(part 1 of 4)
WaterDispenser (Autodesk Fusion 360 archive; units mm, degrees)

design "WaterDispenser" references "Pump"
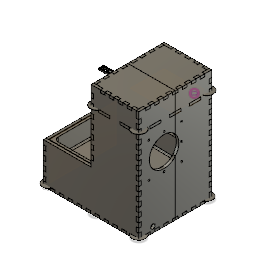
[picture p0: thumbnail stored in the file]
parameter "WaterContainerWidth" = 150
parameter "WaterContainerLenght" = 200
parameter "WaterDispenserHeight" = 75
parameter "WaterSensorFloatDiameter" = 24
parameter "WaterSensorBaseDiameter" = 9.8
parameter "LatexTubeDiameter" = 9.5
parameter "latexTubeInnerDiameter" = 6.5
parameter "WaterContainerCableHoleDiameter" = 14
parameter "WaterSensorCableGap" = 15
parameter "LatexTubeConnectionTightGap" = 0.5
parameter "WaterContainerBorderThickness" = 5
parameter "WaterContainerBorderHeight" = 10
parameter "WaterSensorBaseHeight" = 13
parameter "WaterSensorHeight" = 67.5
parameter "WaterContainerSlopeHeight" = 5
parameter "WaterContainerSensorHoleWith" = 70
parameter "WaterContainerSensorHoleLenght" = 50
parameter "WaterSensorAroundGap" = 10
parameter "WaterContainerHolePumpWidth" = 70
parameter "LatexTubeConnectionLength" = 20
parameter "LatexTubeConnectorToothLenth" = 4
parameter "LatextubeConnectionToothFiletHeight" = 0.4
parameter "WaterContainerSafetyHeightCable" = 20
parameter "WaterContainerElectricHoleDiameter" = 13
parameter "LatexTubeGapHole" = 0.4
parameter "WaterContainerHoleThickness" = 3
parameter "WaterContainerBottomSpaceWire" = 20
parameter "GapBetweenWoodPart" = 0.5
parameter "GapBetweenWaterContainer" = 1
parameter "WaterFallHeight" = 120
parameter "TopContainerHeight" = 40
parameter "WoodThickness" = 5.7
parameter "WoodTooth" = 10
parameter "WaterFallDiameter" = 6
parameter "WaterFallStopperDistance" = 10
parameter "WaterFountainHoleFront" = 15
parameter "WoodConnectionLength" = 25
parameter "AcDistanceHole" = 20
parameter "AcHoleDiameter" = 10
sketch "Sketch1" plane through (0, 0, 0) normal (0, 1, 0) x axis (1, 0, 0)
  line L1 (200, 0) -> (0, 0)
  line L2 (200, 150) -> (200, 0)
  line L3 (0, 150) -> (200, 150)
  line L4 (0, 0) -> (0, 150)
  point P1 (0, 0)
  point P2 (0, 0)
  point P3 (200, 0)
  horizontal L1
  vertical L2
  horizontal L3
  vertical L4
  coincident P1 P2
  dimension "d16" distance P2 P3 = 200 (= "WaterContainerLenght")
  dimension "d17" distance L1 L3 = 150 (= "WaterContainerWidth")
extrude "Extrude1" new body sketch "Sketch1" along normal blind 85 (= "WaterDispenserHeight + WaterContainerBorderHeight")
work_plane "WorkPlane1"
sketch "Sketch2" plane through (100, 42.5, -5) normal (0, 0, 1) x axis (1, 0, 0)
  line L1 (100, -42.5) -> (-100, -42.5)
  line L2 (100, 42.5) -> (100, -42.5)
  line L3 (-100, 42.5) -> (100, 42.5)
  line L4 (-100, -42.5) -> (-100, 42.5)
  line L5 (-95, -42.5) -> (-95, 42.5)
  line L6 (95, -42.5) -> (95, 42.5)
  line L7 (100, -14.5) -> (-100, -14.5)
  line L8 (100, -1.5) -> (-100, -1.5)
  line L9 (100, -27.5) -> (-100, -27.5)
  line L10 (100, 40) -> (-100, 40)
  line L11 (-100, -6.5) -> (100, -6.5)
  line L12 (100, 10) -> (-100, 10)
  line L13 (100, 3.5) -> (-100, 3.5)
  line L14 (-95, 3.5) -> (95, -1.5)
  line L15 (100, -1.5) -> (-100, -1.5)
  line L16 (95, -6.5) -> (-95, -1.5)
  line L17 (45, -42.5) -> (45, -0.1842)
  line L18 (40, -42.5) -> (40, -0.0526)
  line L19 (-100, 42.5) -> (-95, 42.5)
  line L20 (-100, -42.5) -> (-100, 42.5)
  line L21 (-95, -42.5) -> (-100, -42.5)
  line L22 (95, 42.5) -> (-95, 42.5)
  line L23 (-95, -42.5) -> (40, -42.5)
  point P6 (-95, 42.5)
  point P7 (-95, -42.5)
  point P8 (95, 42.5)
  point P9 (95, -42.5)
  point P10 (-100, -14.5)
  point P11 (100, -14.5)
  point P12 (-100, -1.5)
  point P13 (100, -1.5)
  point P14 (-100, -27.5)
  point P15 (100, -27.5)
  point P16 (-100, 40)
  point P17 (100, 40)
  point P18 (100, -6.5)
  point P19 (-100, -6.5)
  point P20 (-100, 10)
  point P21 (100, 10)
  point P22 (-100, 3.5)
  point P23 (100, 3.5)
  point P24 (95, -1.5)
  point P25 (-95, 3.5)
  point P26 (-100, -1.5)
  point P27 (100, -1.5)
  point P28 (-95, -1.5)
  point P29 (95, -6.5)
  point P30 (45, -0.1842)
  point P31 (45, -42.5)
  point P32 (40, -0.0526)
  point P33 (40, -42.5)
  point P5 (-100, 42.5)
  point P34 (-100, 42.5)
  point P2 (-100, -42.5)
  point P35 (-100, -42.5)
  point P36 (-100, -42.5)
  coincident L3 P6
  coincident L1 P7
  perpendicular L1 L5
  coincident L3 P8
  coincident L1 P9
  perpendicular L1 L6
  coincident L4 P10
  coincident L2 P11
  perpendicular L2 L7
  coincident L4 P12
  coincident L2 P13
  perpendicular L2 L8
  coincident L4 P14
  coincident L2 P15
  perpendicular L2 L9
  coincident L4 P16
  coincident L2 P17
  perpendicular L2 L10
  coincident L2 P18
  coincident L4 P19
  perpendicular L4 L11
  coincident L4 P20
  coincident L2 P21
  perpendicular L2 L12
  coincident L4 P22
  coincident L2 P23
  perpendicular L2 L13
  coincident L8 P24
  coincident L6 P24
  coincident L5 P25
  coincident L13 P25
  coincident L4 P26
  coincident L2 P27
  perpendicular L2 L15
  coincident L15 P28
  coincident L5 P28
  coincident L6 P29
  coincident L11 P29
  coincident L14 P30
  coincident L1 P31
  perpendicular L1 L17
  coincident L14 P32
  coincident L1 P33
  perpendicular L1 L18
  coincident P5 P34
  coincident P2 P35
  coincident P2 P36
  dimension "d21" distance L4 L5 = 5 (= "WaterContainerBorderThickness")
  dimension "d22" distance L2 L6 = 5 (= "WaterContainerBorderThickness")
  dimension "d23" distance L1 L8 = 41
  dimension "d24" distance L1 L7 = 28 (= "WaterSensorCableGap + WaterSensorBaseHeight")
  dimension "d29" distance L1 L9 = 15 (= "WaterSensorCableGap")
  dimension "d30" distance L9 L10 = 67.5 (= "WaterSensorHeight")
  dimension "d32" distance L8 L11 = 5 (= "WaterContainerBorderThickness")
  dimension "d33" distance L8 L13 = 5 (= "WaterContainerSlopeHeight")
  dimension "d34" distance L11 L15 = 5 (= "WaterContainerSlopeHeight")
  dimension "d37" distance L6 L17 = 50 (= "WaterContainerSensorHoleLenght")
  dimension "d38" distance L17 L18 = 5 (= "WaterContainerBorderThickness")
extrude "Extrude2" cut sketch "Sketch2" profile of L1 L3 L5 L6 L14 L16 L18 L22 L23 against normal blind 140 (magnitude of "-( WaterContainerWidth - 2 * WaterContainerBorderThickness )")
work_plane "WorkPlane2"
sketch "Sketch4" plane through (100, 20, -75) normal (0, -1, 0) x axis (1, 0, 0)
  line L1 (-95, 70) -> (-95, -70)
  line L2 (40, 70) -> (-95, 70)
  line L3 (40, -70) -> (40, 70)
  line L4 (-95, -70) -> (40, -70)
  line L5 (-100, -75) -> (-100, 75)
  line L6 (100, -75) -> (-100, -75)
  line L7 (100, 75) -> (100, -75)
  line L8 (-100, 75) -> (100, 75)
  line L9 (40, 0) -> (100, 0)
  line L10 (95, -75) -> (95, 75)
  line L11 (73, -75) -> (73, 75)
  line L12 (56, 35) -> (90, 35)
  line L13 (56, -35) -> (56, 35)
  line L14 (90, -35) -> (56, -35)
  line L15 (90, 35) -> (90, -35)
  line L16 (56, -35) -> (90, 35)
  line L17 (90, -35) -> (56, 35)
  point P10 (100, 0)
  point P11 (40, 0)
  point P12 (95, 75)
  point P13 (95, -75)
  point P14 (73, 75)
  point P15 (73, -75)
  point P20 (73, 0)
  point P18 (56, -35)
  point P19 (90, -35)
  midpoint L7 P10
  midpoint L3 P11
  coincident L8 P12
  coincident L6 P13
  perpendicular L6 L10
  coincident L8 P14
  coincident L6 P15
  perpendicular L6 L11
  perpendicular L12 L13
  parallel L12 L14
  parallel L13 L15
  horizontal L12
  coincident L16 P20
  coincident L17 P20
  midpoint L11 P20
  dimension "d44" distance L10 L11 = 22 (= "WaterSensorAroundGap + ( WaterSensorFloatDiameter / 2 )")
  dimension "d45" distance L7 L10 = 5 (= "WaterContainerBorderThickness")
  dimension "d47" distance P18 P19 = 34 (= "WaterSensorFloatDiameter + WaterSensorAroundGap")
  dimension "d48" distance L12 L14 = 70 (= "WaterContainerHolePumpWidth")
extrude "Extrude3" cut sketch "Sketch4" profile of L12 L13 L14 L15 to an object
chamfer "Chamfer4" distance 20
fillet "Fillet7" radius 40
fillet "Fillet8" radius 20.54
fillet "Fillet9" radius 30
fillet "Fillet10" radius 50
sketch "Sketch6" plane through (0, 20, 0) normal (0, 1, 0) x axis (-1, 0, 0)
  line L1 (-156, -110) -> (-190, -110)
  line L2 (-156, -40) -> (-156, -110)
  line L3 (-190, -40) -> (-156, -40)
  line L4 (-156, -75) -> (-190, -75)
  line L5 (-173, -40) -> (-173, -110)
  line L6 (-190, -110) -> (-190, -40)
  circle C1 centre (-173, -75) radius 4.9
  point P9 (-156, -75)
  point P10 (-173, -110)
  point P11 (-173, -40)
  point P12 (-173, -75)
  midpoint L2 P9
  midpoint L1 P10
  midpoint L3 P11
  midpoint L4 P12
  dimension "d78" diameter C1 = 9.8 (= "WaterSensorBaseDiameter")
extrude "Extrude7" cut sketch "Sketch6" profile of C1 to an object
sketch "Sketch7" plane through (0, 0, 0) normal (0, -1, 0) x axis (1, 0, 0)
  line L1 (5, -5) -> (5, -145)
  line L2 (140, -5) -> (5, -5)
  line L3 (140, -145) -> (140, -5)
  line L4 (5, -145) -> (140, -145)
  line L5 (0, -150) -> (0, 0)
  line L6 (200, -150) -> (0, -150)
  line L7 (200, 0) -> (200, -150)
  line L8 (0, 0) -> (200, 0)
  line L9 (5, -5) -> (140, -5)
  line L10 (5, -145) -> (5, -5)
  line L11 (140, -145) -> (5, -145)
  line L12 (140, -5) -> (140, -145)
  line L13 (200, -5) -> (140, -5)
  line L14 (200, -145) -> (140, -145)
  line L15 (195, -145) -> (195, -5)
  circle C1 centre (173, -75) radius 4.9
  point P11 (140, -5)
  point P15 (140, -5)
  point P16 (200, -5)
  point P14 (140, -145)
  point P17 (140, -145)
  point P18 (200, -145)
  point P19 (195, -5)
  point P20 (195, -145)
  coincident P11 P15
  coincident L7 P16
  perpendicular L7 L13
  coincident P14 P17
  coincident L7 P18
  perpendicular L7 L14
  coincident L13 P19
  coincident L14 P20
  perpendicular L14 L15
  dimension "d81" distance L7 L15 = 5 (= "WaterContainerBorderThickness")
extrude "Extrude8" cut sketch "Sketch7" profile of C1 L3 L12 L13 L14 L15 no distance stored
sketch "Sketch8" plane through (140, 0, 0) normal (-1, 0, 0) x axis (0, 0, 1)
  line L1 (-5, 15) -> (-145, 15)
  line L2 (-5, 37.4474) -> (-5, 15)
  line L3 (-145, 37.4474) -> (-5, 37.4474)
  line L4 (-145, 15) -> (-145, 37.4474)
  line L5 (-110, 20) -> (-40, 20)
  line L6 (-38.8581, 22.0197) -> (-111.1419, 22.0197)
  line L7 (-75, 20) -> (-75, 22.0197)
  line L8 (-39.9729, 22.0197) -> (-40, 20)
  line L9 (-75, 19.5953) -> (-50.0021, 19.5953)
  line L10 (-62.5011, 20) -> (-62.5011, 19.5953)
  curve K1 (-40, 20) -> (-38.8581, 22.0197)
  curve K2 (-111.1419, 22.0197) -> (-110, 20)
  circle C1 centre (-62.5011, 23.25) radius 3.25
  circle C2 centre (-62.5011, 23.25) radius 4.75
  point P10 (-75, 22.0197)
  point P11 (-75, 20)
  point P6 (-40, 20)
  point P12 (-40, 20)
  point P13 (-39.9729, 22.0197)
  point P15 (-75, 19.5953)
  point P16 (-62.5011, 19.5953)
  point P17 (-62.5011, 20)
  midpoint L6 P10
  midpoint L5 P11
  coincident P6 P12
  coincident L6 P13
  coincident L7 P15
  perpendicular L7 L9
  midpoint L9 P16
  coincident L5 P17
  perpendicular L5 L10
  coincident P17 C1
  concentric C1 C2
  dimension "d84" diameter C1 = 6.5 (= "latexTubeInnerDiameter")
  dimension "d85" diameter C2 = 9.5 (= "LatexTubeDiameter")
extrude "Extrude9" cut sketch "Sketch8" profile of C1 to an object
extrude "Extrude10" new body sketch "Sketch8" profile of L5 L6 C1 C2 along normal blind 20 (= "LatexTubeConnectionLength")
work_plane "WorkPlane3" AlongDistance -62.501
sketch "Sketch9" plane through (100, 42.5, -62.5011) normal (0, 0, 1) x axis (1, 0, 0)
  line L1 (20, -24) -> (20, -14.5)
  line L2 (40, -24) -> (40, -14.5)
  line L3 (39, -14) -> (25, -14)
  line L4 (40, -14.5) -> (20, -14.5)
  line L5 (24, -14.5) -> (24, -14.4)
  curve K1 (23.3029, -14.1322) -> (20, -14.5)
  line L6 (17, -19.25) -> (40, -19.25)
  arc A1 centre (23.6, -14.4) radius 0.4 clockwise from (23.3029, -14.1322) to (24, -14.4)
  point P2 (20, -14.5)
  point P8 (20, -14.5)
  point P4 (40, -14.5)
  point P9 (40, -14.5)
  point P10 (24, -14.5)
  point P11 (20, -14.5)
  point P13 (40, -19.25)
  point P17 (24, -14.4)
  horizontal L3
  coincident P2 P8
  coincident P4 P9
  coincident L4 P10
  perpendicular L4 L5
  coincident P8 P11
  midpoint L2 P13
  perpendicular L1 L6
  tangent K1 A1
  tangent L5 A1
  dimension "d93" distance P2 L3 = 0.5 (= "LatexTubeConnectionTightGap")
  dimension "d94" distance P8 L5 = 4 (= "LatexTubeConnectorToothLenth")
  dimension "d100" radius A1 = 0.4 (= "LatextubeConnectionToothFiletHeight")
  dimension "d102" distance P10 P17 = 0.1 (= "LatexTubeConnectionTightGap - LatextubeConnectionToothFiletHeight")
work_plane "WorkPlane4" AlongDistance 20 (= "WaterContainerSafetyHeightCable")
sketch "Sketch10" plane through (100, 105, -75) normal (0, 1, 0) x axis (1, 0, 0)
  line L1 (-95, 70) -> (-95, -70)
  line L2 (95, 70) -> (-95, 70)
  line L3 (95, -70) -> (95, 70)
  line L4 (-95, -70) -> (95, -70)
  line L5 (-100, -75) -> (-100, 75)
  line L6 (100, -75) -> (-100, -75)
  line L7 (100, 75) -> (100, -75)
  line L8 (-100, 75) -> (100, 75)
  line L9 (60.169, 60.5) -> (60.169, 70)
  line L10 (87.05, 54.1) -> (95, 54.1)
  circle C1 centre (87.05, 62.05) radius 4.95
  circle C2 centre (87.05, 62.05) radius 7.95
  circle C3 centre (69.669, 60.5) radius 6.5
  circle C4 centre (69.669, 60.5) radius 9.5
  point P14 (60.169, 70)
  point P15 (60.169, 60.5)
  point P16 (95, 54.1)
  point P17 (87.05, 54.1)
  concentric C1 C2
  concentric C3 C4
  tangent L2 C2
  tangent L2 C4
  tangent L3 C2
  tangent C2 C4
  coincident L2 P14
  coincident C4 P15
  tangent C4 L9
  perpendicular L2 L9
  coincident L3 P16
  coincident C2 P17
  tangent C2 L10
  perpendicular L3 L10
  dimension "d108" diameter C1 = 9.9 (= "LatexTubeDiameter + LatexTubeGapHole")
  dimension "d110" distance C1 C2 = 3 (= "WaterContainerHoleThickness")
  dimension "d112" diameter C3 = 13 (= "WaterContainerElectricHoleDiameter")
  dimension "d113" distance C3 C4 = 3 (= "WaterContainerHoleThickness")
extrude "Extrude11" cut sketch "Sketch10" profile of L2 L3 C1 C2 C3 C4 L9 L10 to an object
sketch "Sketch11" plane through (0, 15, 0) normal (0, -1, 0) x axis (1, 0, 0)
  line L1 (195, -5) -> (195, -129.1)
  line L2 (140, -5) -> (195, -5)
  line L3 (140, -145) -> (140, -5)
  line L4 (160.169, -145) -> (140, -145)
  line L5 (160.169, -126) -> (160.169, -145)
  line L6 (195, -126) -> (160.169, -126)
  line L7 (160.169, -135.5) -> (160.169, -145)
  line L8 (195, -129.1) -> (187.05, -129.1)
  line L9 (140, -126) -> (160.169, -126)
  arc A1 centre (169.669, -135.5) radius 9.5 clockwise from (160.169, -135.5) to (179.1314, -136.3438)
  arc A2 centre (187.05, -137.05) radius 7.95 clockwise from (179.1314, -136.3438) to (187.05, -129.1)
  circle C1 centre (173, -75) radius 4.9
  arc A3 centre (169.669, -135.5) radius 9.5 clockwise from (160.169, -135.5) to (179.1314, -136.3438)
  arc A4 centre (187.05, -137.05) radius 7.95 clockwise from (179.1314, -136.3438) to (187.05, -129.1)
  point P16 (160.169, -145)
  point P18 (195, -126)
  point P21 (140, -126)
  coincident L4 P16
  perpendicular L4 L5
  coincident L1 P18
  perpendicular L1 L6
  tangent A1 L5
  tangent A3 L6
  coincident L3 P21
  perpendicular L3 L9
extrude "Extrude12" cut sketch "Sketch11" profile of A1 A2 L1 L3 L4 A3 A4 L5 L6 L7 L8 L9 no distance stored
extrude "Extrude13" new body sketch "Sketch10" profile of L2 L3 C1 C2 C3 C4 L9 L10 to an object
fillet "Fillet12" radius 5
combine "Combine1"
fillet "Fillet13" radius 8
extrude "Extrude14" add of existing geometry to an object
extrude "Extrude15" add of existing geometry to an object
fillet "Fillet14" radius 10
fillet "Fillet15" radius 3
fillet "Fillet16" radius 3
fillet "Fillet18" radius 10
work_plane "WorkPlane5" AlongDistance 1 (= "GapBetweenWaterContainer")
work_plane "WorkPlane6" AlongDistance 1 (= "GapBetweenWaterContainer")
sketch "Sketch12" plane through (100, 42.5, 1) normal (0, 0, 1) x axis (1, 0, 0)
  line L1 (-106.7, -48.2) -> (-106.7, 42.5)
  line L2 (106.7, 202.5) -> (106.7, -48.2)
  line L3 (0, 202.5) -> (106.7, 202.5)
  line L4 (0, 42.5) -> (0, 202.5)
  line L5 (-106.7, 42.5) -> (0, 42.5)
  line L6 (100, -42.5) -> (-100, -42.5)
  line L7 (100, 42.5) -> (100, -42.5)
  line L8 (-100, 42.5) -> (100, 42.5)
  line L9 (-100, -42.5) -> (-100, 42.5)
  line L10 (106.7, -48.2) -> (-106.7, -48.2)
  point P11 (-100, 42.5)
  point P1 (0, 0)
  point P4 (106.7, -48.2)
  point P13 (106.7, -48.2)
  point P3 (-106.7, -48.2)
  point P12 (-106.7, -48.2)
  vertical L1
  perpendicular L1 L3
  perpendicular L1 L5
  coincident L5 P11
  coincident P1 L4
  perpendicular L1 L10
  coincident P4 P13
  coincident P3 P12
  dimension "d137" distance L1 L9 = 6.7 (= "GapBetweenWaterContainer + WoodThickness")
  dimension "d138" distance L2 L7 = 6.7 (= "GapBetweenWaterContainer + WoodThickness")
  dimension "d140" distance L3 L8 = 160 (= "WaterFallHeight + TopContainerHeight")
  dimension "d145" distance L6 L10 = 5.7 (= "WoodThickness")
sketch "Sketch13" plane through (-1, 42.5, -75) normal (-1, 0, 0) x axis (0, 0, -1)
  line L1 (-76, 48.2) -> (-76, -42.5)
  line L2 (-75, 42.5) -> (75, 42.5)
  line L3 (75, -42.5) -> (75, 42.5)
  line L4 (-75, -42.5) -> (75, -42.5)
  line L5 (-81.7, -42.5) -> (81.7, -42.5)
  line L6 (81.7, 48.2) -> (-81.7, 48.2)
  line L7 (81.7, -42.5) -> (81.7, 48.2)
  line L8 (-81.7, 48.2) -> (-81.7, -42.5)
  line L9 (0, 48.2) -> (0, -42.5)
  point P7 (-75, -42.5)
  point P11 (-81.7, -42.5)
  point P12 (0, -42.5)
  point P13 (0, 48.2)
  horizontal L5
  horizontal L6
  vertical L7
  coincident P7 L5
  perpendicular L5 L8
  coincident L5 P11
  midpoint L4 P12
  midpoint L6 P13
  dimension "d149" distance L3 L7 = 6.7 (= "WoodThickness + GapBetweenWaterContainer")
  dimension "d150" distance L2 L6 = 5.7 (= "WoodThickness")
  dimension "d151" distance L1 L8 = 5.7 (= "WoodThickness")
extrude "Extrude1" new body sketch "Sketch12" along normal blind 5.7 (= "WoodThickness")
sketch "Sketch1" plane through (0, 0, 6.7) normal (0, 0, 1) x axis (1, 0, 0)
  line L1 (206.7, -5.7) -> (-6.7, -5.7)
  line L2 (206.7, 245) -> (206.7, -5.7)
  line L3 (100, 245) -> (206.7, 245)
  line L4 (100, 85) -> (100, 245)
  line L5 (-6.7, 85) -> (100, 85)
  line L6 (-6.7, -5.7) -> (-6.7, 85)
  line L7 (-1, 85) -> (-6.7, 85)
  line L8 (-1, 75) -> (-1, 85)
  line L9 (-6.7, 75) -> (-1, 75)
  line L10 (-6.7, 85) -> (-6.7, 75)
  line L11 (-1, 75) -> (-6.7, 75)
  line L12 (-1, 65) -> (-1, 75)
  line L13 (-6.7, 65) -> (-1, 65)
  line L14 (-6.7, 75) -> (-6.7, 65)
  line L15 (-6.7, 55) -> (-1, 55)
  line L16 (-1, 45) -> (-1, 55)
  line L17 (-6.7, 45) -> (-1, 45)
  line L18 (-6.7, 55) -> (-6.7, 45)
  line L19 (-6.7, 35) -> (-1, 35)
  line L20 (-1, 25) -> (-1, 35)
  line L21 (-6.7, 25) -> (-1, 25)
  line L22 (-6.7, 35) -> (-6.7, 25)
  line L23 (-6.7, 15) -> (-1, 15)
  line L24 (-1, 5) -> (-1, 15)
  line L25 (-6.7, 5) -> (-1, 5)
  line L26 (-6.7, 15) -> (-6.7, 5)
  point P7 (-6.7, 85)
  point P8 (-6.7, 85)
  point P11 (-6.7, 75)
  point P9 (-1, 85)
  point P14 (-6.7, 65)
  horizontal L7
  vertical L8
  horizontal L9
  vertical L10
  coincident P7 P8
  horizontal L11
  vertical L12
  horizontal L13
  vertical L14
  dimension "d155" distance P8 P11 = 10 (= "WoodTooth")
  dimension "d156" distance P8 P9 = 5.7 (= "WoodThickness")
  dimension "d157" distance P11 P14 = 10 (= "WoodTooth")
  dimension "d158" distance L12 L14 = 5.7 (= "WoodThickness")
  dimension "d163" R-Pattern1-uDistance = -60
  dimension "d164" R-Pattern1-vDistance = -20 (= "-2 * WoodTooth")
extrude "Extrude3" cut sketch "Sketch1" profile of L6 L9 L11 L12 L13 L14 L15 L16 L17 L18 L19 L20 L21 L22 L23 L24 L25 L26 to an object
sketch "Sketch3" plane through (0, 0, 6.7) normal (0, 0, 1) x axis (1, 0, 0)
  line L1 (-1, 55) -> (-6.7, 55)
  line L2 (-1, 45) -> (-1, 55)
  line L3 (-6.7, 45) -> (-1, 45)
  line L4 (-6.7, 35) -> (-6.7, 45)
  line L5 (-1, 35) -> (-6.7, 35)
  line L6 (-1, 25) -> (-1, 35)
  line L7 (-6.7, 25) -> (-1, 25)
  line L8 (-6.7, 15) -> (-6.7, 25)
  line L9 (-1, 15) -> (-6.7, 15)
  line L10 (-1, 5) -> (-1, 15)
  line L11 (-6.7, 5) -> (-1, 5)
  line L12 (-6.7, -5.7) -> (-6.7, 5)
  line L13 (206.7, -5.7) -> (-6.7, -5.7)
  line L14 (206.7, 245) -> (206.7, -5.7)
  line L15 (100, 245) -> (206.7, 245)
  line L16 (100, 85) -> (100, 245)
  line L17 (-6.7, 85) -> (100, 85)
  line L18 (-6.7, 75) -> (-6.7, 85)
  line L19 (-1, 75) -> (-6.7, 75)
  line L20 (-1, 65) -> (-1, 75)
  line L21 (-6.7, 65) -> (-1, 65)
  line L22 (-6.7, 55) -> (-6.7, 65)
  line L23 (9, -5.7) -> (-1, -5.7)
  line L24 (9, 0) -> (9, -5.7)
  line L25 (-1, 0) -> (9, 0)
  line L26 (-1, -5.7) -> (-1, 0)
  line L27 (-1, -5.7) -> (-1, 85)
  line L28 (9, 0) -> (19, 0)
  line L29 (9, -5.7) -> (9, 0)
  line L30 (19, 0) -> (19, -5.7)
  line L31 (19, -5.7) -> (9, -5.7)
  line L32 (19, 0) -> (29, 0)
  line L33 (19, -5.7) -> (19, 0)
  line L34 (29, 0) -> (29, -5.7)
  line L35 (29, -5.7) -> (19, -5.7)
  line L36 (29, 0) -> (39, 0)
  line L37 (29, -5.7) -> (29, 0)
  line L38 (39, 0) -> (39, -5.7)
  line L39 (39, -5.7) -> (29, -5.7)
  line L40 (39, 0) -> (49, 0)
  line L41 (39, -5.7) -> (39, 0)
  line L42 (49, 0) -> (49, -5.7)
  line L43 (49, -5.7) -> (39, -5.7)
  line L44 (49, 0) -> (59, 0)
  line L45 (49, -5.7) -> (49, 0)
  line L46 (59, 0) -> (59, -5.7)
  line L47 (59, -5.7) -> (49, -5.7)
  line L48 (59, 0) -> (69, 0)
  line L49 (59, -5.7) -> (59, 0)
  line L50 (69, 0) -> (69, -5.7)
  line L51 (69, -5.7) -> (59, -5.7)
  line L52 (69, 0) -> (79, 0)
  line L53 (69, -5.7) -> (69, 0)
  line L54 (79, 0) -> (79, -5.7)
  line L55 (79, -5.7) -> (69, -5.7)
  line L56 (79, 0) -> (89, 0)
  line L57 (79, -5.7) -> (79, 0)
  line L58 (89, 0) -> (89, -5.7)
  line L59 (89, -5.7) -> (79, -5.7)
  line L60 (89, 0) -> (99, 0)
  line L61 (89, -5.7) -> (89, 0)
  line L62 (99, 0) -> (99, -5.7)
  line L63 (99, -5.7) -> (89, -5.7)
  line L64 (99, 0) -> (109, 0)
  line L65 (99, -5.7) -> (99, 0)
  line L66 (109, 0) -> (109, -5.7)
  line L67 (109, -5.7) -> (99, -5.7)
  line L68 (109, 0) -> (119, 0)
  line L69 (109, -5.7) -> (109, 0)
  line L70 (119, 0) -> (119, -5.7)
  line L71 (119, -5.7) -> (109, -5.7)
  line L72 (119, 0) -> (129, 0)
  line L73 (119, -5.7) -> (119, 0)
  line L74 (129, 0) -> (129, -5.7)
  line L75 (129, -5.7) -> (119, -5.7)
  line L76 (129, 0) -> (139, 0)
  line L77 (129, -5.7) -> (129, 0)
  line L78 (139, 0) -> (139, -5.7)
  line L79 (139, -5.7) -> (129, -5.7)
  line L80 (139, 0) -> (149, 0)
  line L81 (139, -5.7) -> (139, 0)
  line L82 (149, 0) -> (149, -5.7)
  line L83 (149, -5.7) -> (139, -5.7)
  line L84 (149, 0) -> (159, 0)
  line L85 (149, -5.7) -> (149, 0)
  line L86 (159, 0) -> (159, -5.7)
  line L87 (159, -5.7) -> (149, -5.7)
  line L88 (159, 0) -> (169, 0)
  line L89 (159, -5.7) -> (159, 0)
  line L90 (169, 0) -> (169, -5.7)
  line L91 (169, -5.7) -> (159, -5.7)
  line L92 (169, 0) -> (179, 0)
  line L93 (169, -5.7) -> (169, 0)
  line L94 (179, 0) -> (179, -5.7)
  line L95 (179, -5.7) -> (169, -5.7)
  line L96 (179, 0) -> (189, 0)
  line L97 (179, -5.7) -> (179, 0)
  line L98 (189, 0) -> (189, -5.7)
  line L99 (189, -5.7) -> (179, -5.7)
  line L100 (189, 0) -> (199, 0)
  line L101 (189, -5.7) -> (189, 0)
  line L102 (199, 0) -> (199, -5.7)
  line L103 (199, -5.7) -> (189, -5.7)
  line L104 (201, 0) -> (206.7, 0)
  line L105 (201, 10) -> (201, 0)
  line L106 (206.7, 10) -> (201, 10)
  line L107 (206.7, 0) -> (206.7, 10)
  line L108 (206.7, 20) -> (201, 20)
  line L109 (201, 10) -> (206.7, 10)
  line L110 (201, 20) -> (201, 10)
  line L111 (206.7, 10) -> (206.7, 20)
  line L112 (206.7, 30) -> (201, 30)
  line L113 (201, 20) -> (206.7, 20)
  line L114 (201, 30) -> (201, 20)
  line L115 (206.7, 20) -> (206.7, 30)
  line L116 (206.7, 40) -> (201, 40)
  line L117 (201, 30) -> (206.7, 30)
  line L118 (201, 40) -> (201, 30)
  line L119 (206.7, 30) -> (206.7, 40)
  line L120 (206.7, 50) -> (201, 50)
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  point P24 (-1, -5.7)
  point P27 (-1, 0)
  point P106 (206.7, 0)
  point P102 (199, 0)
  point P242 (100, 239.3)
  point P16 (206.7, 245)
  point P243 (206.7, 245)
  point P244 (206.7, 245)
  point P25 (9, -5.7)
  point P107 (201, 0)
  point P109 (206.7, 10)
  point P202 (201, 239.3)
  point P205 (201, 245)
  point P203 (191, 239.3)
  point P245 (105.7, 239.3)
  point P247 (100, 229.3)
  horizontal L23
  vertical L24
  horizontal L25
  vertical L26
  coincident L13 P24
  coincident P27 L27
  horizontal L104
  vertical L105
  horizontal L106
  vertical L107
  coincident L14 P106
  coincident P102 L104
  coincident L16 P242
  coincident P16 P243
  coincident P16 P244
  dimension "d189" distance P24 P27 = 5.7 (= "WoodThickness")
  dimension "d190" distance P24 P25 = 10 (= "WoodTooth")
  dimension "d197" distance P106 P107 = 5.7 (= "WoodThickness")
  dimension "d198" distance P106 P109 = 10 (= "WoodTooth")
  dimension "d203" distance P202 P205 = 5.7 (= "WoodThickness")
  dimension "d204" distance P202 P203 = 10 (= "WoodTooth")
  dimension "d209" distance P242 P245 = 5.7 (= "WoodThickness")
  dimension "d210" distance P242 P247 = 10 (= "WoodTooth")
  dimension "d193" R-Pattern1-uDistance = 10 (= "WoodTooth")
  dimension "d194" R-Pattern1-vDistance = 0
  dimension "d201" R-Pattern2-uDistance = 0
  dimension "d202" R-Pattern2-vDistance = 10 (= "WoodTooth")
  dimension "d208" R-Pattern3-vDistance = 0
  dimension "d213" R-Pattern4-uDistance = 0
extrude "Extrude7" cut sketch "Sketch3" to an object
work_plane "WorkPlane1"
mirror "Mirror1"
sketch "Sketch4" plane through (0, 0, 0) normal (-1, 0, 0) x axis (0, 0, 1)
  line L1 (0, 0) -> (-150, 0)
  line L2 (0, 85) -> (0, 0)
  line L3 (-150, 85) -> (0, 85)
  line L4 (-150, 0) -> (-150, 85)
work_plane "WorkPlane1" sketch "Sketch4" AlongDistance 1 (= "GapBetweenWaterContainer")
sketch "Sketch2" plane through (-1, 42.5, -75) normal (-1, 0, 0) x axis (0, 0, -1)
  line L1 (-81.7, -32.5) -> (-76, -32.5)
  line L2 (-81.7, -42.5) -> (-81.7, -32.5)
  line L3 (-76, -42.5) -> (-81.7, -42.5)
  line L4 (-76, -32.5) -> (-76, -42.5)
  line L5 (-81.7, -12.5) -> (-76, -12.5)
  line L6 (-81.7, -22.5) -> (-81.7, -12.5)
  line L7 (-76, -22.5) -> (-81.7, -22.5)
  line L8 (-76, -12.5) -> (-76, -22.5)
  line L9 (-76, -2.5) -> (-81.7, -2.5)
  line L10 (-76, 7.5) -> (-76, -2.5)
  line L11 (-81.7, 7.5) -> (-76, 7.5)
  line L12 (-81.7, -2.5) -> (-81.7, 7.5)
  line L13 (-76, 17.5) -> (-81.7, 17.5)
  line L14 (-76, 27.5) -> (-76, 17.5)
  line L15 (-81.7, 27.5) -> (-76, 27.5)
  line L16 (-81.7, 17.5) -> (-81.7, 27.5)
  line L17 (-76, 37.5) -> (-81.7, 37.5)
  line L18 (-76, 48.2) -> (-76, 37.5)
  line L19 (-81.7, 48.2) -> (-76, 48.2)
  line L20 (-81.7, 37.5) -> (-81.7, 48.2)
  line L21 (-75, 42.5) -> (75, 42.5)
  line L22 (-75, -42.5) -> (-75, 42.5)
  line L23 (75, -42.5) -> (-75, -42.5)
  line L24 (75, 42.5) -> (75, -42.5)
  line L25 (0, 42.5) -> (0, -42.5)
  line L26 (0, 48.2) -> (0, 42.5)
  line L27 (-76, 48.2) -> (0, 48.2)
  line L28 (-76, 48.2) -> (-76, 37.5)
  line L29 (-81.7, 37.5) -> (-76, 37.5)
  line L30 (-81.7, 27.5) -> (-81.7, 37.5)
  line L31 (-76, 27.5) -> (-81.7, 27.5)
  line L32 (-76, 17.5) -> (-76, 27.5)
  line L33 (-81.7, 17.5) -> (-76, 17.5)
  line L34 (-81.7, 7.5) -> (-81.7, 17.5)
  line L35 (-76, 7.5) -> (-81.7, 7.5)
  line L36 (-76, -2.5) -> (-76, 7.5)
  line L37 (-76, -2.5) -> (-81.7, -2.5)
  line L38 (-81.7, -12.5) -> (-81.7, -2.5)
  line L39 (-76, -12.5) -> (-81.7, -12.5)
  line L40 (-76, -22.5) -> (-76, -12.5)
  line L41 (-81.7, -22.5) -> (-76, -22.5)
  line L42 (-81.7, -32.5) -> (-81.7, -22.5)
  line L43 (-76, -32.5) -> (-81.7, -32.5)
  line L44 (-76, -42.5) -> (-76, -32.5)
  line L45 (0, -42.5) -> (-76, -42.5)
  line L46 (-76, 42.5) -> (-75, 42.5)
  line L47 (-66, 42.5) -> (-76, 42.5)
  line L48 (-66, 48.2) -> (-66, 42.5)
  line L49 (-76, 48.2) -> (-66, 48.2)
  line L50 (-76, 42.5) -> (-76, 48.2)
  line L51 (-56, 42.5) -> (-66, 42.5)
  line L52 (-56, 48.2) -> (-56, 42.5)
  line L53 (-66, 48.2) -> (-56, 48.2)
  line L54 (-66, 42.5) -> (-66, 48.2)
  line L55 (-46, 42.5) -> (-56, 42.5)
  line L56 (-46, 48.2) -> (-46, 42.5)
  line L57 (-56, 48.2) -> (-46, 48.2)
  line L58 (-56, 42.5) -> (-56, 48.2)
  line L59 (-36, 42.5) -> (-46, 42.5)
  line L60 (-36, 48.2) -> (-36, 42.5)
  line L61 (-46, 48.2) -> (-36, 48.2)
  line L62 (-46, 42.5) -> (-46, 48.2)
  line L63 (-26, 42.5) -> (-36, 42.5)
  line L64 (-26, 48.2) -> (-26, 42.5)
  line L65 (-36, 48.2) -> (-26, 48.2)
  line L66 (-36, 42.5) -> (-36, 48.2)
  line L67 (-16, 42.5) -> (-26, 42.5)
  line L68 (-16, 48.2) -> (-16, 42.5)
  line L69 (-26, 48.2) -> (-16, 48.2)
  line L70 (-26, 42.5) -> (-26, 48.2)
  line L71 (-6, 42.5) -> (-16, 42.5)
  line L72 (-6, 48.2) -> (-6, 42.5)
  line L73 (-16, 48.2) -> (-6, 48.2)
  line L74 (-16, 42.5) -> (-16, 48.2)
  point P26 (0, -42.5)
  point P27 (0, 42.5)
  point P20 (-76, 48.2)
  point P29 (-76, 48.2)
  point P19 (-76, 37.5)
  point P30 (-76, 37.5)
  point P31 (-76, 37.5)
  point P18 (-81.7, 37.5)
  point P32 (-81.7, 37.5)
  point P33 (-81.7, 37.5)
  point P17 (-81.7, 27.5)
  point P34 (-81.7, 27.5)
  point P35 (-81.7, 27.5)
  point P16 (-76, 27.5)
  point P36 (-76, 27.5)
  point P37 (-76, 27.5)
  point P15 (-76, 17.5)
  point P38 (-76, 17.5)
  point P14 (-81.7, 17.5)
  point P39 (-81.7, 17.5)
  point P40 (-81.7, 17.5)
  point P13 (-81.7, 7.5)
  point P41 (-81.7, 7.5)
  point P12 (-76, 7.5)
  point P42 (-76, 7.5)
  point P11 (-76, -2.5)
  point P43 (-76, -2.5)
  point P10 (-81.7, -2.5)
  point P44 (-81.7, -2.5)
  point P45 (-76, -2.5)
  point P46 (-81.7, -2.5)
  point P7 (-81.7, -12.5)
  point P47 (-81.7, -12.5)
  point P48 (-81.7, -12.5)
  point P6 (-76, -12.5)
  point P49 (-76, -12.5)
  point P9 (-76, -22.5)
  point P50 (-76, -22.5)
  point P8 (-81.7, -22.5)
  point P51 (-81.7, -22.5)
  point P52 (-81.7, -22.5)
  point P3 (-81.7, -32.5)
  point P53 (-81.7, -32.5)
  point P54 (-81.7, -32.5)
  point P2 (-76, -32.5)
  point P55 (-76, -32.5)
  point P56 (-76, -32.5)
  point P5 (-76, -42.5)
  point P57 (-76, -42.5)
  point P58 (-76, -42.5)
  point P23 (-75, 42.5)
  point P59 (-75, 42.5)
  point P60 (-76, 42.5)
  point P61 (-66, 42.5)
  point P63 (-76, 48.2)
  midpoint L23 P26
  midpoint L21 P27
  perpendicular L19 L26
  coincident P20 P29
  perpendicular L20 L27
  coincident P19 P30
  coincident P19 P31
  coincident P18 P32
  coincident P18 P33
  coincident P17 P34
  coincident P17 P35
  coincident P16 P36
  coincident P16 P37
  coincident P15 P38
  coincident P14 P39
  coincident P14 P40
  coincident P13 P41
  coincident P12 P42
  coincident P11 P43
  coincident P10 P44
  coincident P11 P45
  coincident P10 P46
  coincident P7 P47
  coincident P7 P48
  coincident P6 P49
  coincident P9 P50
  coincident P8 P51
  coincident P8 P52
  coincident P3 P53
  coincident P3 P54
  coincident P2 P55
  coincident P2 P56
  coincident P5 P57
  coincident P5 P58
  coincident P23 P59
  coincident L18 P60
  perpendicular L18 L46
  horizontal L47
  vertical L48
  horizontal L49
  vertical L50
  dimension "d219" distance P60 P61 = 10 (= "WoodTooth")
  dimension "d220" distance P60 P63 = 5.7 (= "WoodThickness")
  dimension "d223" R-Pattern1-uDistance = 10 (= "WoodTooth")
  dimension "d224" R-Pattern1-vDistance = 0
extrude "Extrude1" new body sketch "Sketch2" profile of L1 L4 L5 L7 L8 L9 L10 L11 L13 L14 L15 L17 L18 L21 L22 L23 L25 L27 L28 L29 L30 L31 L32 L33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 along normal blind 5.7 (= "WoodThickness")
work_plane "WorkPlane2" AlongDistance -81.7
mirror "Mirror1"
copy_paste "CutPaste1"
copy_paste "CutPaste2"
sketch "Sketch2" plane through (105.7, 0, 0) normal (-1, 0, 0) x axis (0, 0, 1)
  line L1 (-151, 229.3) -> (-151, 219.3)
  line L2 (-156.7, 229.3) -> (-151, 229.3)
  line L3 (-156.7, 219.3) -> (-156.7, 229.3)
  line L4 (-151, 219.3) -> (-156.7, 219.3)
  line L5 (6.7, 229.3) -> (1, 229.3)
  line L6 (6.7, 245) -> (6.7, 229.3)
  line L7 (1, 245) -> (6.7, 245)
  line L8 (1, 229.3) -> (1, 245)
  line L9 (1, 219.3) -> (6.7, 219.3)
  line L10 (1, 209.3) -> (1, 219.3)
  line L11 (6.7, 209.3) -> (1, 209.3)
  line L12 (6.7, 219.3) -> (6.7, 209.3)
  line L13 (1, 199.3) -> (6.7, 199.3)
  line L14 (1, 189.3) -> (1, 199.3)
  line L15 (6.7, 189.3) -> (1, 189.3)
  line L16 (6.7, 199.3) -> (6.7, 189.3)
  line L17 (6.7, 169.3) -> (1, 169.3)
  line L18 (6.7, 179.3) -> (6.7, 169.3)
  line L19 (1, 179.3) -> (6.7, 179.3)
  line L20 (1, 169.3) -> (1, 179.3)
  line L21 (6.7, 149.3) -> (1, 149.3)
  line L22 (6.7, 159.3) -> (6.7, 149.3)
  line L23 (1, 159.3) -> (6.7, 159.3)
  line L24 (1, 149.3) -> (1, 159.3)
  line L25 (1, 139.3) -> (6.7, 139.3)
  line L26 (1, 129.3) -> (1, 139.3)
  line L27 (6.7, 129.3) -> (1, 129.3)
  line L28 (6.7, 139.3) -> (6.7, 129.3)
  line L29 (1, 119.3) -> (6.7, 119.3)
  line L30 (1, 109.3) -> (1, 119.3)
  line L31 (6.7, 109.3) -> (1, 109.3)
  line L32 (6.7, 119.3) -> (6.7, 109.3)
  line L33 (1, 99.3) -> (6.7, 99.3)
  line L34 (1, 85) -> (1, 99.3)
  line L35 (6.7, 85) -> (1, 85)
  line L36 (6.7, 99.3) -> (6.7, 85)
  line L37 (-151, 229.3) -> (-156.7, 229.3)
  line L38 (-151, 245) -> (-151, 229.3)
  line L39 (-156.7, 245) -> (-151, 245)
  line L40 (-156.7, 229.3) -> (-156.7, 245)
  line L41 (1, 245) -> (-151, 245)
  line L42 (-75, 85) -> (-75, 245)
  line L43 (1, 85) -> (-75, 85)
  line L44 (6.7, 99.3) -> (1, 99.3)
  line L45 (1, 85) -> (1, 99.3)
  line L46 (6.7, 109.3) -> (6.7, 99.3)
  line L47 (1, 109.3) -> (6.7, 109.3)
  line L48 (1, 119.3) -> (1, 109.3)
  line L49 (6.7, 119.3) -> (1, 119.3)
  line L50 (6.7, 129.3) -> (6.7, 119.3)
  line L51 (1, 129.3) -> (6.7, 129.3)
  line L52 (1, 139.3) -> (1, 129.3)
  line L53 (6.7, 139.3) -> (1, 139.3)
  line L54 (6.7, 149.3) -> (6.7, 139.3)
  line L55 (1, 149.3) -> (6.7, 149.3)
  line L56 (1, 159.3) -> (1, 149.3)
  line L57 (6.7, 159.3) -> (1, 159.3)
  line L58 (6.7, 169.3) -> (6.7, 159.3)
  line L59 (1, 169.3) -> (6.7, 169.3)
  line L60 (1, 179.3) -> (1, 169.3)
  line L61 (6.7, 179.3) -> (1, 179.3)
  line L62 (6.7, 189.3) -> (6.7, 179.3)
  line L63 (1, 189.3) -> (6.7, 189.3)
  line L64 (1, 199.3) -> (1, 189.3)
  line L65 (6.7, 199.3) -> (1, 199.3)
  line L66 (6.7, 209.3) -> (6.7, 199.3)
  line L67 (1, 209.3) -> (6.7, 209.3)
  line L68 (1, 219.3) -> (1, 209.3)
  line L69 (6.7, 219.3) -> (1, 219.3)
  line L70 (6.7, 229.3) -> (6.7, 219.3)
  line L71 (1, 229.3) -> (6.7, 229.3)
  line L72 (1, 245) -> (1, 229.3)
  line L73 (-75, 245) -> (1, 245)
  point P40 (-151, 245)
  point P42 (-151, 245)
  point P9 (1, 245)
  point P43 (1, 245)
  point P44 (-75, 245)
  point P36 (1, 85)
  point P46 (1, 85)
  point P35 (1, 99.3)
  point P47 (1, 99.3)
  point P34 (6.7, 99.3)
  point P48 (6.7, 99.3)
  point P49 (1, 99.3)
  point P50 (6.7, 99.3)
  point P33 (6.7, 109.3)
  point P51 (6.7, 109.3)
  point P52 (6.7, 109.3)
  point P32 (1, 109.3)
  point P53 (1, 109.3)
  point P54 (1, 109.3)
  point P31 (1, 119.3)
  point P55 (1, 119.3)
  point P30 (6.7, 119.3)
  point P56 (6.7, 119.3)
  point P57 (6.7, 119.3)
  point P29 (6.7, 129.3)
  point P58 (6.7, 129.3)
  point P28 (1, 129.3)
  point P59 (1, 129.3)
  point P27 (1, 139.3)
  point P60 (1, 139.3)
  point P26 (6.7, 139.3)
  point P61 (6.7, 139.3)
  point P23 (6.7, 149.3)
  point P62 (6.7, 149.3)
  point P22 (1, 149.3)
  point P63 (1, 149.3)
  point P64 (1, 149.3)
  point P25 (1, 159.3)
  point P65 (1, 159.3)
  point P66 (1, 159.3)
  point P24 (6.7, 159.3)
  point P67 (6.7, 159.3)
  point P19 (6.7, 169.3)
  point P68 (6.7, 169.3)
  point P18 (1, 169.3)
  point P69 (1, 169.3)
  point P21 (1, 179.3)
  point P70 (1, 179.3)
  point P20 (6.7, 179.3)
  point P71 (6.7, 179.3)
  point P17 (6.7, 189.3)
  point P72 (6.7, 189.3)
  point P16 (1, 189.3)
  point P73 (1, 189.3)
  point P15 (1, 199.3)
  point P74 (1, 199.3)
  point P14 (6.7, 199.3)
  point P75 (6.7, 199.3)
  point P76 (6.7, 199.3)
  point P13 (6.7, 209.3)
  point P77 (6.7, 209.3)
  point P12 (1, 209.3)
  point P78 (1, 209.3)
  point P11 (1, 219.3)
  point P79 (1, 219.3)
  point P10 (6.7, 219.3)
  point P80 (6.7, 219.3)
  point P81 (6.7, 219.3)
  point P7 (6.7, 229.3)
  point P82 (6.7, 229.3)
  point P6 (1, 229.3)
  point P83 (1, 229.3)
  point P84 (1, 245)
  coincident P40 P42
  coincident P9 P43
  midpoint L41 P44
  perpendicular L35 L42
  coincident P36 P46
  perpendicular L34 L43
  coincident P35 P47
  coincident P34 P48
  coincident P35 P49
  coincident P34 P50
  coincident P33 P51
  coincident P33 P52
  coincident P32 P53
  coincident P32 P54
  coincident P31 P55
  coincident P30 P56
  coincident P30 P57
  coincident P29 P58
  coincident P28 P59
  coincident P27 P60
  coincident P26 P61
  coincident P23 P62
  coincident P22 P63
  coincident P22 P64
  coincident P25 P65
  coincident P25 P66
  coincident P24 P67
  coincident P19 P68
  coincident P18 P69
  coincident P21 P70
  coincident P20 P71
  coincident P17 P72
  coincident P16 P73
  coincident P15 P74
  coincident P14 P75
  coincident P14 P76
  coincident P13 P77
  coincident P12 P78
  coincident P11 P79
  coincident P10 P80
  coincident P10 P81
  coincident P7 P82
  coincident P6 P83
  coincident P9 P84
extrude "Extrude1" new body sketch "Sketch2" profile of L5 L8 L9 L10 L11 L13 L14 L15 L17 L19 L20 L21 L23 L24 L25 L26 L27 L29 L30 L31 L33 L34 L42 L43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 along normal blind 5.7 (= "WoodThickness")
sketch "Sketch3" plane through (100, 0, 0) normal (-1, 0, 0) x axis (0, 0, 1)
  line L1 (6.7, 99.3) -> (1, 99.3)
  line L2 (6.7, 109.3) -> (6.7, 99.3)
  line L3 (1, 109.3) -> (6.7, 109.3)
  line L4 (1, 119.3) -> (1, 109.3)
  line L5 (6.7, 119.3) -> (1, 119.3)
  line L6 (6.7, 129.3) -> (6.7, 119.3)
  line L7 (1, 129.3) -> (6.7, 129.3)
  line L8 (1, 139.3) -> (1, 129.3)
  line L9 (6.7, 139.3) -> (1, 139.3)
  line L10 (6.7, 149.3) -> (6.7, 139.3)
  line L11 (1, 149.3) -> (6.7, 149.3)
  line L12 (1, 159.3) -> (1, 149.3)
  line L13 (6.7, 159.3) -> (1, 159.3)
  line L14 (6.7, 169.3) -> (6.7, 159.3)
  line L15 (1, 169.3) -> (6.7, 169.3)
  line L16 (1, 179.3) -> (1, 169.3)
  line L17 (6.7, 179.3) -> (1, 179.3)
  line L18 (6.7, 189.3) -> (6.7, 179.3)
  line L19 (1, 189.3) -> (6.7, 189.3)
  line L20 (1, 199.3) -> (1, 189.3)
  line L21 (6.7, 199.3) -> (1, 199.3)
  line L22 (6.7, 209.3) -> (6.7, 199.3)
  line L23 (1, 209.3) -> (6.7, 209.3)
  line L24 (1, 219.3) -> (1, 209.3)
  line L25 (6.7, 219.3) -> (1, 219.3)
  line L26 (6.7, 229.3) -> (6.7, 219.3)
  line L27 (1, 229.3) -> (6.7, 229.3)
  line L28 (1, 245) -> (1, 229.3)
  line L29 (-75, 245) -> (1, 245)
  line L30 (-75, 85) -> (-75, 245)
  line L31 (1, 85) -> (-75, 85)
  line L32 (1, 99.3) -> (1, 85)
  line L33 (-9, 245) -> (1, 245)
  line L34 (-9, 239.3) -> (-9, 245)
  line L35 (1, 239.3) -> (-9, 239.3)
  line L36 (1, 245) -> (1, 239.3)
  line L37 (-19, 239.3) -> (-19, 245)
  line L38 (-19, 245) -> (-9, 245)
  line L39 (-9, 245) -> (-9, 239.3)
  line L40 (-9, 239.3) -> (-19, 239.3)
  line L41 (-29, 239.3) -> (-29, 245)
  line L42 (-29, 245) -> (-19, 245)
  line L43 (-19, 245) -> (-19, 239.3)
  line L44 (-19, 239.3) -> (-29, 239.3)
  line L45 (-39, 239.3) -> (-39, 245)
  line L46 (-39, 245) -> (-29, 245)
  line L47 (-29, 245) -> (-29, 239.3)
  line L48 (-29, 239.3) -> (-39, 239.3)
  line L49 (-49, 239.3) -> (-49, 245)
  line L50 (-49, 245) -> (-39, 245)
  line L51 (-39, 245) -> (-39, 239.3)
  line L52 (-39, 239.3) -> (-49, 239.3)
  line L53 (-59, 239.3) -> (-59, 245)
  line L54 (-59, 245) -> (-49, 245)
  line L55 (-49, 245) -> (-49, 239.3)
  line L56 (-49, 239.3) -> (-59, 239.3)
  line L57 (-69, 239.3) -> (-69, 245)
  line L58 (-69, 245) -> (-59, 245)
  line L59 (-59, 245) -> (-59, 239.3)
  line L60 (-59, 239.3) -> (-69, 239.3)
  line L61 (-75, 239.3) -> (-69, 239.3)
  point P30 (1, 245)
  point P34 (1, 245)
  point P62 (-75, 239.3)
  point P35 (-9, 245)
  point P37 (1, 239.3)
  horizontal L33
  vertical L34
  horizontal L35
  vertical L36
  coincident P30 P34
  coincident L30 P62
  perpendicular L30 L61
  dimension "d229" distance P34 P35 = 10 (= "WoodTooth")
  dimension "d230" distance P34 P37 = 5.7 (= "WoodThickness")
  dimension "d234" R-Pattern1-vDistance = 0
extrude "Extrude2" cut sketch "Sketch3" profile of L29 L30 L34 L37 L38 L39 L40 L41 L43 L45 L46 L47 L48 L49 L51 L53 L54 L55 L56 L57 L59 L61 to an object
work_plane "WorkPlane1" AlongDistance -81.7
mirror "Mirror1"
sketch "Sketch1" plane through (201, 0, 0) normal (1, 0, 0) x axis (0, 0, -1)
  line L1 (-1, 200) -> (-1, 190)
  line L2 (-6.7, 200) -> (-1, 200)
  line L3 (-6.7, 190) -> (-6.7, 200)
  line L4 (-1, 190) -> (-6.7, 190)
  line L5 (-1, 245) -> (-1, 230)
  line L6 (-6.7, 245) -> (-1, 245)
  line L7 (-6.7, 230) -> (-6.7, 245)
  line L8 (-1, 230) -> (-6.7, 230)
  line L9 (-1, 220) -> (-1, 210)
  line L10 (-6.7, 220) -> (-1, 220)
  line L11 (-6.7, 210) -> (-6.7, 220)
  line L12 (-1, 210) -> (-6.7, 210)
  line L13 (-1, 180) -> (-1, 170)
  line L14 (-6.7, 180) -> (-1, 180)
  line L15 (-6.7, 170) -> (-6.7, 180)
  line L16 (-1, 170) -> (-6.7, 170)
  line L17 (-1, 160) -> (-1, 150)
  line L18 (-6.7, 160) -> (-1, 160)
  line L19 (-6.7, 150) -> (-6.7, 160)
  line L20 (-1, 150) -> (-6.7, 150)
  line L21 (-1, 140) -> (-1, 130)
  line L22 (-6.7, 140) -> (-1, 140)
  line L23 (-6.7, 130) -> (-6.7, 140)
  line L24 (-1, 130) -> (-6.7, 130)
  line L25 (-1, 120) -> (-1, 110)
  line L26 (-6.7, 120) -> (-1, 120)
  line L27 (-6.7, 110) -> (-6.7, 120)
  line L28 (-1, 110) -> (-6.7, 110)
  line L29 (-1, 100) -> (-1, 90)
  line L30 (-6.7, 100) -> (-1, 100)
  line L31 (-6.7, 90) -> (-6.7, 100)
  line L32 (-1, 90) -> (-6.7, 90)
  line L33 (-1, 80) -> (-1, 70)
  line L34 (-6.7, 80) -> (-1, 80)
  line L35 (-6.7, 70) -> (-6.7, 80)
  line L36 (-1, 70) -> (-6.7, 70)
  line L37 (-1, 60) -> (-1, 50)
  line L38 (-6.7, 60) -> (-1, 60)
  line L39 (-6.7, 50) -> (-6.7, 60)
  line L40 (-1, 50) -> (-6.7, 50)
  line L41 (-1, 40) -> (-1, 30)
  line L42 (-6.7, 40) -> (-1, 40)
  line L43 (-6.7, 30) -> (-6.7, 40)
  line L44 (-1, 30) -> (-6.7, 30)
  line L45 (-1, 20) -> (-1, 10)
  line L46 (-6.7, 20) -> (-1, 20)
  line L47 (-6.7, 10) -> (-6.7, 20)
  line L48 (-1, 10) -> (-6.7, 10)
  line L49 (-6.7, 10) -> (-1, 10)
  line L50 (-6.7, -5.7) -> (-6.7, 10)
  line L51 (-1, -5.7) -> (-6.7, -5.7)
  line L52 (-1, 10) -> (-1, -5.7)
  line L53 (151, 10) -> (156.7, 10)
  line L54 (151, -5.7) -> (151, 10)
  line L55 (156.7, -5.7) -> (151, -5.7)
  line L56 (156.7, 10) -> (156.7, -5.7)
  line L57 (151, -5.7) -> (-1, -5.7)
  line L58 (75, 245) -> (75, -5.7)
  line L59 (-6.7, 245) -> (75, 245)
  line L60 (-6.7, 230) -> (-6.7, 245)
  line L61 (-1, 230) -> (-6.7, 230)
  line L62 (-1, 220) -> (-1, 230)
  line L63 (-6.7, 220) -> (-1, 220)
  line L64 (-6.7, 210) -> (-6.7, 220)
  line L65 (-1, 210) -> (-6.7, 210)
  line L66 (-1, 200) -> (-1, 210)
  line L67 (-6.7, 200) -> (-1, 200)
  line L68 (-6.7, 190) -> (-6.7, 200)
  line L69 (-1, 190) -> (-6.7, 190)
  line L70 (-1, 190) -> (-1, 180)
  line L71 (-6.7, 180) -> (-1, 180)
  line L72 (-6.7, 170) -> (-6.7, 180)
  line L73 (-1, 170) -> (-6.7, 170)
  line L74 (-1, 160) -> (-1, 170)
  line L75 (-6.7, 160) -> (-1, 160)
  line L76 (-6.7, 150) -> (-6.7, 160)
  line L77 (-1, 150) -> (-6.7, 150)
  line L78 (-1, 140) -> (-1, 150)
  line L79 (-6.7, 140) -> (-1, 140)
  line L80 (-6.7, 130) -> (-6.7, 140)
  line L81 (-1, 130) -> (-6.7, 130)
  line L82 (-1, 120) -> (-1, 130)
  line L83 (-6.7, 120) -> (-1, 120)
  line L84 (-6.7, 110) -> (-6.7, 120)
  line L85 (-1, 110) -> (-6.7, 110)
  line L86 (-1, 100) -> (-1, 110)
  line L87 (-6.7, 100) -> (-1, 100)
  line L88 (-6.7, 90) -> (-6.7, 100)
  line L89 (-1, 90) -> (-6.7, 90)
  line L90 (-1, 80) -> (-1, 90)
  line L91 (-6.7, 80) -> (-1, 80)
  line L92 (-6.7, 70) -> (-6.7, 80)
  line L93 (-1, 70) -> (-6.7, 70)
  line L94 (-1, 60) -> (-1, 70)
  line L95 (-6.7, 60) -> (-1, 60)
  line L96 (-6.7, 50) -> (-6.7, 60)
  line L97 (-1, 50) -> (-6.7, 50)
  line L98 (-1, 40) -> (-1, 50)
  line L99 (-6.7, 40) -> (-1, 40)
  line L100 (-6.7, 30) -> (-6.7, 40)
  line L101 (-1, 30) -> (-6.7, 30)
  line L102 (-1, 20) -> (-1, 30)
  line L103 (-6.7, 20) -> (-1, 20)
  line L104 (-6.7, 10) -> (-6.7, 20)
  line L105 (-1, 10) -> (-6.7, 10)
  line L106 (-1, -5.7) -> (-1, 10)
  line L107 (75, -5.7) -> (-1, -5.7)
  point P53 (-1, -5.7)
  point P58 (-1, -5.7)
  point P56 (151, -5.7)
  point P59 (151, -5.7)
  point P60 (75, -5.7)
  point P8 (-6.7, 245)
  point P62 (-6.7, 245)
  point P9 (-6.7, 230)
  point P63 (-6.7, 230)
  point P6 (-1, 230)
  point P64 (-1, 230)
  point P11 (-1, 220)
  point P65 (-1, 220)
  point P12 (-6.7, 220)
  point P66 (-6.7, 220)
  point P67 (-6.7, 220)
  point P13 (-6.7, 210)
  point P68 (-6.7, 210)
  point P69 (-6.7, 210)
  point P10 (-1, 210)
  point P70 (-1, 210)
  point P71 (-1, 210)
  point P3 (-1, 200)
  point P72 (-1, 200)
  point P4 (-6.7, 200)
  point P73 (-6.7, 200)
  point P5 (-6.7, 190)
  point P74 (-6.7, 190)
  point P2 (-1, 190)
  point P75 (-1, 190)
  point P15 (-1, 180)
  point P76 (-1, 180)
  point P77 (-1, 190)
  point P16 (-6.7, 180)
  point P78 (-6.7, 180)
  point P17 (-6.7, 170)
  point P79 (-6.7, 170)
  point P80 (-6.7, 170)
  point P14 (-1, 170)
  point P81 (-1, 170)
  point P19 (-1, 160)
  point P82 (-1, 160)
  point P83 (-1, 160)
  point P20 (-6.7, 160)
  point P84 (-6.7, 160)
  point P21 (-6.7, 150)
  point P85 (-6.7, 150)
  point P18 (-1, 150)
  point P86 (-1, 150)
  point P87 (-1, 150)
  point P23 (-1, 140)
  point P88 (-1, 140)
  point P24 (-6.7, 140)
  point P89 (-6.7, 140)
  point P25 (-6.7, 130)
  point P90 (-6.7, 130)
  point P22 (-1, 130)
  point P91 (-1, 130)
  point P27 (-1, 120)
  point P92 (-1, 120)
  point P93 (-1, 120)
  point P28 (-6.7, 120)
  point P94 (-6.7, 120)
  point P29 (-6.7, 110)
  point P95 (-6.7, 110)
  point P26 (-1, 110)
  point P96 (-1, 110)
  point P97 (-1, 110)
  point P31 (-1, 100)
  point P98 (-1, 100)
  point P99 (-1, 100)
  point P32 (-6.7, 100)
  point P100 (-6.7, 100)
  point P101 (-6.7, 100)
  point P33 (-6.7, 90)
  point P102 (-6.7, 90)
  point P30 (-1, 90)
  point P103 (-1, 90)
  point P104 (-1, 90)
  point P35 (-1, 80)
  point P105 (-1, 80)
  point P36 (-6.7, 80)
  point P106 (-6.7, 80)
  point P107 (-6.7, 80)
  point P37 (-6.7, 70)
  point P108 (-6.7, 70)
  point P34 (-1, 70)
  point P109 (-1, 70)
  point P39 (-1, 60)
  point P110 (-1, 60)
  point P111 (-1, 60)
  point P40 (-6.7, 60)
  point P112 (-6.7, 60)
  point P41 (-6.7, 50)
  point P113 (-6.7, 50)
  point P38 (-1, 50)
  point P114 (-1, 50)
  point P115 (-1, 50)
  point P43 (-1, 40)
  point P116 (-1, 40)
  point P44 (-6.7, 40)
  point P117 (-6.7, 40)
  point P45 (-6.7, 30)
  point P118 (-6.7, 30)
  point P119 (-6.7, 30)
  point P42 (-1, 30)
  point P120 (-1, 30)
  point P47 (-1, 20)
  point P121 (-1, 20)
  point P122 (-1, 20)
  point P48 (-6.7, 20)
  point P123 (-6.7, 20)
  point P124 (-6.7, 20)
  point P49 (-6.7, 10)
  point P125 (-6.7, 10)
  point P51 (-6.7, 10)
  point P126 (-6.7, 10)
  point P46 (-1, 10)
  point P127 (-1, 10)
  point P128 (-1, 10)
  point P129 (-1, -5.7)
  coincident P53 P58
  coincident P56 P59
  midpoint L57 P60
  perpendicular L6 L58
  coincident P8 P62
  perpendicular L7 L59
  coincident P9 P63
  coincident P6 P64
  coincident P11 P65
  coincident P12 P66
  coincident P12 P67
  coincident P13 P68
  coincident P13 P69
  coincident P10 P70
  coincident P10 P71
  coincident P3 P72
  coincident P4 P73
  coincident P5 P74
  coincident P2 P75
  coincident P15 P76
  coincident P2 P77
  coincident P16 P78
  coincident P17 P79
  coincident P17 P80
  coincident P14 P81
  coincident P19 P82
  coincident P19 P83
  coincident P20 P84
  coincident P21 P85
  coincident P18 P86
  coincident P18 P87
  coincident P23 P88
  coincident P24 P89
  coincident P25 P90
  coincident P22 P91
  coincident P27 P92
  coincident P27 P93
  coincident P28 P94
  coincident P29 P95
  coincident P26 P96
  coincident P26 P97
  coincident P31 P98
  coincident P31 P99
  coincident P32 P100
  coincident P32 P101
  coincident P33 P102
  coincident P30 P103
  coincident P30 P104
  coincident P35 P105
  coincident P36 P106
  coincident P36 P107
  coincident P37 P108
  coincident P34 P109
  coincident P39 P110
  coincident P39 P111
  coincident P40 P112
  coincident P41 P113
  coincident P38 P114
  coincident P38 P115
  coincident P43 P116
  coincident P44 P117
  coincident P45 P118
  coincident P45 P119
  coincident P42 P120
  coincident P47 P121
  coincident P47 P122
  coincident P48 P123
  coincident P48 P124
  coincident P49 P125
  coincident P51 P126
  coincident P46 P127
  coincident P46 P128
  coincident P53 P129
extrude "Extrude1" new body sketch "Sketch1" profile of L1 L2 L3 L4 L5 L6 L7 L8 L9 L10 L11 L12 L13 L14 L15 L16 L17 L18 L19 L20 L21 L22 L23 L24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 along normal blind 5.7 (= "WoodThickness")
